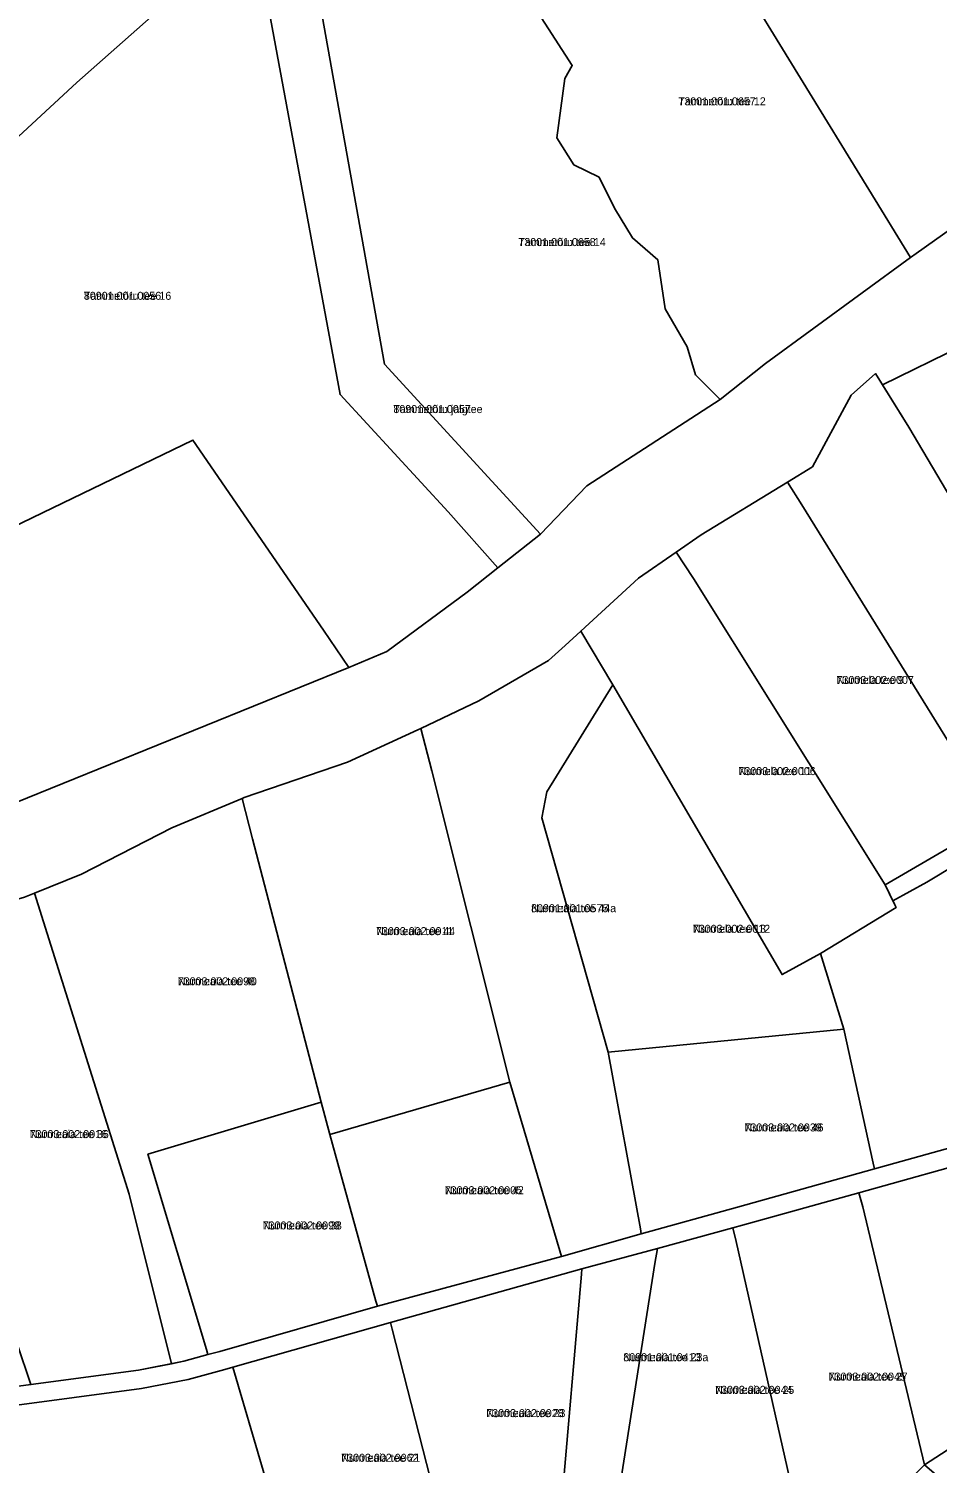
# Model space of a CAD drawing. Extents: x 524000 to 564260, y 6469338 to 6496391.
# Drawn here: x 526890.8 to 527061.2, y 6477525.9 to 6477794.8 of the extents above; entities that cross this region are included whole.
import ezdxf

# ---------------------------------------------------------------- set-up
doc = ezdxf.new("R2010")
doc.units = 0
for name, color, linetype in [('L_AADRESS', 7, 'Continuous'), ('PIIR', 7, 'Continuous'), ('TUNNUS', 7, 'Continuous')]:
    doc.layers.add(name, color=color, linetype=linetype)

msp = doc.modelspace()

# ---------------------------------------------------------------- linework, layer by layer
at = {"layer": 'PIIR'}
for points in [[(527213.1, 6478042.55), (527147.5, 6477989.63), (527133.13, 6477978.03), (527125.21, 6477971.64), (527105.49, 6477955.73), (527088.84, 6477942.09), (527072.55, 6477929.2), (527052.99, 6477914.01), (527014.52, 6477882.85), (527002.6, 6477873.42), (526964.99, 6477841.78), (526939.46, 6477819.74), (526931.63, 6477812.84), (526921.27, 6477803.64), (526899.89, 6477784.68), (526873.76, 6477760.55)], [(526888.32, 6477649.68), (526950.85, 6477675.06), (526957.96, 6477678.04), (526973.04, 6477689.13), (526978.77, 6477693.69), (526986.78, 6477700.05), (526995.46, 6477709.06), (527020.5, 6477725.25), (527028.95, 6477732.03), (527056.18, 6477751.87), (527057.25, 6477752.65), (527064.12, 6477757.5), (527085.25, 6477770.01), (527087.52, 6477771.35), (527094.74, 6477776.35), (527108.42, 6477781.12), (527112.92, 6477784.31), (527115.83, 6477786.37), (527127.79, 6477792.82), (527138.62, 6477797.97)], [(527065.98, 6477735.39), (527050.91, 6477728.01), (527049.58, 6477730.12), (527045.06, 6477726.1), (527037.79, 6477712.63), (527033.11, 6477709.77), (527016.89, 6477699.87), (527012.25, 6477696.65), (527005.19, 6477691.75), (526994.35, 6477681.87), (526991.4, 6477679.17), (526988.31, 6477676.36), (526975.24, 6477668.76), (526964.38, 6477663.61), (526963.81, 6477663.34), (526950.64, 6477657.32), (526931.25, 6477650.65), (526930.85, 6477650.48), (526917.67, 6477645.01), (526900.76, 6477636.28), (526891.91, 6477632.72), (526890.06, 6477631.97)], [(527080.9, 6477647.87), (527059.2, 6477634.82), (527052.83, 6477631.31), (527051.39, 6477634.3), (527072.35, 6477646.49)], [(526874.47, 6477538.42), (526891.24, 6477540.65), (526911.4, 6477543.34), (526919.94, 6477545.02), (526924.43, 6477546.26), (526926.66, 6477546.86), (526956.21, 6477555.32), (526990.73, 6477564.65), (527005.68, 6477568.92), (527023.75, 6477573.91), (527049.41, 6477581.07), (527074.81, 6477588.11)], [(527071.03, 6477583.43), (527046.47, 6477576.6), (527024.68, 6477570.54), (527022.85, 6477570.03), (527008.71, 6477566.13), (526994.56, 6477562.37), (526958.7, 6477552.26), (526929.11, 6477543.91), (526927.6, 6477543.49), (526920.74, 6477541.62), (526911.97, 6477539.89), (526874.99, 6477534.96)]]:
    msp.add_lwpolyline(points, dxfattribs=at)
for points in [[(527021.72, 6477868.28), (527077.11, 6477782.59), (527085.25, 6477770.01), (527064.12, 6477757.5), (527057.25, 6477752.65), (527056.18, 6477751.87), (527048.35, 6477764.63), (526997.09, 6477848.14)], [(526997.09, 6477848.14), (527048.35, 6477764.63), (527056.18, 6477751.87), (527028.95, 6477732.03), (527020.5, 6477725.25), (527015.83, 6477729.87), (527014.31, 6477735.14), (527010.19, 6477742.23), (527008.79, 6477751.46), (527004.07, 6477755.55), (527000.65, 6477761.1), (526997.77, 6477766.96), (526993.07, 6477769.22), (526989.84, 6477774.31), (526991.34, 6477785.43), (526992.75, 6477787.85), (526986.34, 6477797.76), (526969.11, 6477824.41)], [(526969.11, 6477824.41), (526986.34, 6477797.76), (526992.75, 6477787.85), (526991.34, 6477785.43), (526989.84, 6477774.31), (526993.07, 6477769.22), (526997.77, 6477766.96), (527000.65, 6477761.1), (527004.07, 6477755.55), (527008.79, 6477751.46), (527010.19, 6477742.23), (527014.31, 6477735.14), (527015.83, 6477729.87), (527020.5, 6477725.25), (526995.46, 6477709.06), (526986.78, 6477700.05), (526977.67, 6477709.97), (526957.55, 6477731.87), (526944.78, 6477803.16)], [(526931.63, 6477812.84), (526939.46, 6477819.74), (526944.78, 6477803.16), (526957.55, 6477731.87), (526977.67, 6477709.97), (526986.78, 6477700.05), (526978.77, 6477693.69), (526969.49, 6477704.23), (526949.21, 6477726.19), (526935.84, 6477798.37)], [(526921.27, 6477803.64), (526931.63, 6477812.84), (526935.84, 6477798.37), (526949.21, 6477726.19), (526969.49, 6477704.23), (526978.77, 6477693.69), (526973.04, 6477689.13), (526957.96, 6477678.04), (526950.85, 6477675.06), (526946.08, 6477682.01), (526921.63, 6477717.65), (526883.92, 6477699.46), (526852.2, 6477738.12), (526851.38, 6477739.11), (526873.76, 6477760.55), (526899.89, 6477784.68)], [(526950.85, 6477675.06), (526888.32, 6477649.68), (526869.12, 6477639.01), (526801.86, 6477597.7), (526784.64, 6477585.76), (526733.03, 6477536.06), (526706.87, 6477508.61), (526704.89, 6477510.14), (526654.45, 6477550.84), (526851.38, 6477739.11), (526852.2, 6477738.12), (526883.92, 6477699.46), (526921.63, 6477717.65), (526946.08, 6477682.01)], [(527050.91, 6477728.01), (527065.98, 6477735.39), (527074.71, 6477738.34), (527076.07, 6477736.03), (527114.02, 6477671.8), (527102.76, 6477666.17), (527096.41, 6477662.75), (527094.62, 6477661.25), (527093.73, 6477662.6), (527082.49, 6477682.97), (527078.87, 6477681.22), (527055.88, 6477720.07)], [(527033.11, 6477709.77), (527037.79, 6477712.63), (527045.06, 6477726.1), (527049.58, 6477730.12), (527055.88, 6477720.07), (527078.87, 6477681.22), (527082.49, 6477682.97), (527093.73, 6477662.6), (527094.62, 6477661.25), (527092.3, 6477659.3), (527079.19, 6477650.92), (527072.35, 6477646.49), (527035.82, 6477705.55)], [(527012.25, 6477696.65), (527016.89, 6477699.87), (527033.11, 6477709.77), (527035.82, 6477705.55), (527072.35, 6477646.49), (527051.39, 6477634.3), (527015.45, 6477691.74)], [(526994.35, 6477681.87), (527005.19, 6477691.75), (527012.25, 6477696.65), (527015.45, 6477691.74), (527051.39, 6477634.3), (527053.2, 6477630.55), (527053.45, 6477630.04), (527039.32, 6477621.44), (527032.09, 6477617.48), (527000.36, 6477671.78)], [(526964.38, 6477663.61), (526975.24, 6477668.76), (526988.31, 6477676.36), (526991.4, 6477679.17), (526994.35, 6477681.87), (527000.36, 6477671.78), (526988, 6477651.75), (526987.05, 6477646.85), (526999.51, 6477602.97), (527005.53, 6477569.82), (527005.68, 6477568.92), (526990.73, 6477564.65), (526990.4, 6477565.74), (526981.07, 6477597.32), (526966.44, 6477655.7)], [(526987.05, 6477646.85), (526988, 6477651.75), (527000.36, 6477671.78), (527032.09, 6477617.48), (527039.32, 6477621.44), (527043.65, 6477607.26), (526999.51, 6477602.97)], [(526930.85, 6477650.48), (526931.25, 6477650.65), (526950.64, 6477657.32), (526963.81, 6477663.34), (526964.38, 6477663.61), (526966.44, 6477655.7), (526981.07, 6477597.32), (526947.31, 6477587.49), (526945.65, 6477593.58), (526932.81, 6477642.92)], [(527049.14, 6477582.17), (527043.65, 6477607.26), (527039.32, 6477621.44), (527053.45, 6477630.04), (527052.83, 6477631.31), (527059.2, 6477634.82), (527080.9, 6477647.87), (527086.34, 6477650.7), (527088.51, 6477651.18), (527089.89, 6477651.11), (527091.43, 6477649.33), (527104.16, 6477631.62), (527115.62, 6477616.22), (527118.89, 6477612.29), (527127.58, 6477604.53), (527125.89, 6477603.25), (527119.15, 6477601.17), (527102.99, 6477595.86), (527074.81, 6477588.11), (527049.41, 6477581.07)], [(526945.65, 6477593.58), (526913.18, 6477583.8), (526924.15, 6477547.22), (526924.43, 6477546.26), (526919.94, 6477545.02), (526917.6, 6477544.56), (526917.42, 6477545.3), (526909.68, 6477576.31), (526894.3, 6477625.16), (526891.91, 6477632.72), (526900.76, 6477636.28), (526917.67, 6477645.01), (526930.85, 6477650.48), (526932.81, 6477642.92)], [(526864.43, 6477619.04), (526871.22, 6477622.98), (526873.63, 6477624.5), (526886.68, 6477630.98), (526890.06, 6477631.97), (526891.91, 6477632.72), (526894.3, 6477625.16), (526909.68, 6477576.31), (526917.6, 6477544.56), (526911.4, 6477543.34), (526891.24, 6477540.65), (526868.13, 6477609.23)], [(526846.53, 6477598.21), (526843.75, 6477605.46), (526845.43, 6477606.67), (526857.31, 6477614.91), (526864.43, 6477619.04), (526868.13, 6477609.23), (526891.24, 6477540.65), (526874.47, 6477538.42), (526866.24, 6477537), (526866.04, 6477537.58), (526853.72, 6477579.42)], [(527005.53, 6477569.82), (526999.51, 6477602.97), (527043.65, 6477607.26), (527049.14, 6477582.17), (527049.41, 6477581.07), (527023.75, 6477573.91), (527005.68, 6477568.92)], [(526956.21, 6477555.32), (526955.94, 6477556.28), (526947.31, 6477587.49), (526981.07, 6477597.32), (526990.4, 6477565.74), (526990.73, 6477564.65)], [(526955.94, 6477556.28), (526956.21, 6477555.32), (526926.66, 6477546.86), (526924.43, 6477546.26), (526924.15, 6477547.22), (526913.18, 6477583.8), (526945.65, 6477593.58), (526947.31, 6477587.49)], [(527047.22, 6477573.95), (527046.47, 6477576.6), (527071.03, 6477583.43), (527071.78, 6477580.42), (527080.58, 6477539.74), (527058.76, 6477525.63)], [(527023.47, 6477567.47), (527022.85, 6477570.03), (527024.68, 6477570.54), (527046.47, 6477576.6), (527047.22, 6477573.95), (527058.76, 6477525.63), (527037.66, 6477504.63)], [(527001.43, 6477519.93), (527008.21, 6477563.36), (527008.71, 6477566.13), (527022.85, 6477570.03), (527023.47, 6477567.47), (527037.66, 6477504.63), (527024.18, 6477498.54), (527013.24, 6477522.51)], [(526994.56, 6477562.37), (527008.71, 6477566.13), (527008.21, 6477563.36), (527001.43, 6477519.93), (527013.24, 6477522.51), (527024.18, 6477498.54), (527009.82, 6477473.06), (526980.46, 6477513.33), (526990.7, 6477517.36), (526994.47, 6477561.34)], [(526958.7, 6477552.26), (526994.56, 6477562.37), (526994.47, 6477561.34), (526990.7, 6477517.36), (526980.46, 6477513.33), (526969.76, 6477509.01), (526959.01, 6477551.06)], [(526953.62, 6477501.54), (526940.51, 6477505.19), (526929.11, 6477543.91), (526958.7, 6477552.26), (526959.01, 6477551.06), (526969.76, 6477509.01)], [(526884.87, 6477431.89), (526868.42, 6477459.86), (526853.51, 6477480.95), (526837.37, 6477517.65), (526837.09, 6477518.26), (526842.11, 6477523.5), (526847.24, 6477527.03), (526851.68, 6477528.93), (526867.45, 6477533.69), (526874.99, 6477534.96), (526911.97, 6477539.89), (526920.74, 6477541.62), (526927.6, 6477543.49), (526929.11, 6477543.91), (526940.51, 6477505.19), (526953.62, 6477501.54), (526973, 6477471.2), (526949.71, 6477454.5), (526964.86, 6477435.07), (526958.5, 6477430), (526953.26, 6477427.73), (526916.44, 6477398.45), (526890.55, 6477425.42)], [(527065.57, 6477518.84), (527062.16, 6477522.74), (527061.47, 6477523.32), (527058.76, 6477525.63), (527080.58, 6477539.74), (527088.74, 6477540.41), (527132.38, 6477500.06), (527113.17, 6477484.7), (527109.22, 6477488.12), (527069.33, 6477524.66)]]:
    msp.add_lwpolyline(points, close=True, dxfattribs=at)

# ---------------------------------------------------------------- texts
at = {"layer": 'L_AADRESS'}
for s, p in [('Tammetõru tee 12', (527012.64, 6477780.4)), ('Tammetõru tee 14', (526982.64, 6477754.02)), ('Tammetõru tee 16', (526901.18, 6477743.95)), ('Tammetõru jalgtee', (526959.21, 6477722.72)), ('Nurmela tee 9', (527042.3, 6477671.95)), ('Nurmela tee 11', (527023.9, 6477654.87)), ('Nurmeaia tee 44a', (526985.03, 6477629.18)), ('Nurmeaia tee 44', (526955.96, 6477624.88)), ('Nurmela tee 13', (527015.35, 6477625.32)), ('Nurmeaia tee 40', (526918.78, 6477615.48)), ('Nurmeaia tee 46', (527025.03, 6477588.09)), ('Nurmeaia tee 36', (526891.02, 6477586.84)), ('Nurmeaia tee 42', (526968.84, 6477576.32)), ('Nurmeaia tee 38', (526934.7, 6477569.72)), ('Nurmeaia tee 23a', (527002.32, 6477545.03)), ('Nurmeaia tee 25', (527019.54, 6477538.91)), ('Nurmeaia tee 27', (527040.8, 6477541.39)), ('Nurmeaia tee 23', (526976.63, 6477534.55)), ('Nurmeaia tee 21', (526949.43, 6477526.18))]:
    msp.add_text(s, height=1.5, dxfattribs=at).set_placement(p)
at = {"layer": 'TUNNUS'}
for s, p in [('73001:001:0657', (527012.64, 6477780.4)), ('73001:001:0658', (526982.64, 6477754.02)), ('80901:001:0056', (526901.18, 6477743.95)), ('80901:001:0057', (526959.21, 6477722.72)), ('73003:002:0007', (527042.3, 6477671.95)), ('73003:002:0006', (527023.9, 6477654.87)), ('80901:001:0575', (526985.03, 6477629.18)), ('73003:002:0011', (526955.96, 6477624.88)), ('73003:002:0012', (527015.35, 6477625.32)), ('73003:002:0098', (526918.78, 6477615.48)), ('73003:002:0039', (527025.03, 6477588.09)), ('73003:002:0016', (526891.02, 6477586.84)), ('73003:002:0005', (526968.84, 6477576.32)), ('73003:002:0099', (526934.7, 6477569.72)), ('80901:001:0413', (527002.32, 6477545.03)), ('73003:002:0044', (527019.54, 6477538.91)), ('73003:002:0045', (527040.8, 6477541.39)), ('73003:002:0028', (526976.63, 6477534.55)), ('73003:002:0062', (526949.43, 6477526.18))]:
    msp.add_text(s, height=1.5, dxfattribs=at).set_placement(p)

doc.saveas('drawing.dxf')
